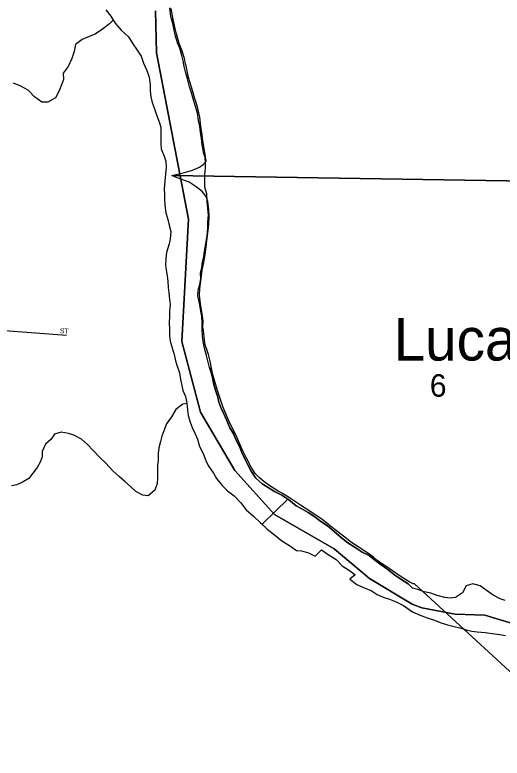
# Model space of a CAD drawing. Extents: x 1624196 to 2029251, y 146837 to 440034.
# Drawn here: x 1822196 to 1826991, y 309103 to 316418 of the extents above; entities that cross this region are included whole.
import ezdxf

# ---------------------------------------------------------------- set-up
doc = ezdxf.new("R2010")
doc.units = 0
for name, color, linetype in [('GM_X_Major_River', 7, 'Continuous'), ('GM_X_Minor_River', 7, 'Continuous'), ('GM_X_Section', 7, 'Continuous'), ('GM_X_Section_Text', 7, 'Continuous'), ('GM_X_Township', 7, 'Continuous'), ('GM_X_Township_Subdivision', 7, 'Continuous'), ('GM_X_Township_Subdivision_Text', 7, 'Continuous'), ('GM_X_Unincorporated_Text', 7, 'Continuous')]:
    doc.layers.add(name, color=color, linetype=linetype)

msp = doc.modelspace()

# ---------------------------------------------------------------- linework, layer by layer
at = {"layer": 'GM_X_Major_River'}
for p, q in [((1824628.7, 311404.7), (1824881.1, 311652.2)), ((1824881.1, 311652.2), (1824628.7, 311404.7))]:
    msp.add_line(p, q, dxfattribs=at)
for points in [[(1823091.5, 316466.6), (1823139.2, 316404.1), (1823183, 316337.6), (1823242.7, 316269), (1823314.6, 316202.4), (1823356.3, 316133.9), (1823392, 316081.5), (1823437.8, 316013), (1823461.4, 315942.6), (1823495, 315870.1), (1823516.7, 315803.8), (1823528.2, 315731.5), (1823527.8, 315669.2), (1823533.5, 315611), (1823545.2, 315556.8), (1823564.9, 315502.5), (1823590.5, 315434.1), (1823614.2, 315363.7), (1823631.9, 315311.4), (1823633.5, 315255.2), (1823633.2, 315205), (1823630.8, 315150.8), (1823636.5, 315098.6), (1823664.1, 315028.2), (1823679.9, 314978), (1823683.5, 314919.7), (1823679, 314851.5), (1823670.6, 314781.3), (1823666, 314705.1), (1823667.7, 314650.9), (1823667.4, 314600.7), (1823671, 314546.5), (1823682.6, 314470.2), (1823696.3, 314417.9), (1823713.9, 314349.6), (1823729.5, 314287.3), (1823725, 314213), (1823714.7, 314163), (1823688, 314080.8), (1823681.6, 314016.6), (1823679.2, 313956.4), (1823684.9, 313904.2), (1823694.6, 313850), (1823702.2, 313793.8), (1823705.8, 313733.5), (1823709.5, 313681.3), (1823717.1, 313619.1), (1823722.8, 313568.8), (1823718.4, 313502.6), (1823718, 313450.5), (1823715.6, 313390.3), (1823717.2, 313320), (1823716.8, 313259.8), (1823724.5, 313207.6), (1823742.1, 313141.3), (1823761.7, 313074.9), (1823777.4, 313012.6), (1823793.1, 312960.3), (1823814.8, 312896), (1823824.4, 312829.7)], [(1824112.2, 312948.4), (1824098.5, 312998.6), (1824082.8, 313067), (1824063.2, 313137.3), (1824049.6, 313203.6), (1824041.9, 313255.9), (1824040.4, 313328.1), (1824038.7, 313380.3), (1824035.2, 313452.6), (1824025.5, 313502.8), (1824011.9, 313579.2), (1823996.4, 313653.5), (1824000.7, 313707.7), (1824017.2, 313765.8), (1824025.6, 313819.9), (1824023.9, 313878.1), (1824034.3, 313930.2), (1824042.7, 313988.4), (1824055.1, 314038.5), (1824063.4, 314088.6), (1824084.4, 314224.9), (1824090.7, 314275.1), (1824093.1, 314327.2), (1824095.4, 314377.4), (1824099.9, 314449.6), (1824094.3, 314513.9), (1824088.7, 314582.1), (1824083.2, 314656.4), (1824065.6, 314722.8), (1824063.9, 314775), (1824066.4, 314845.2), (1824070.8, 314909.4), (1824073.2, 314959.5), (1824067.5, 315013.8), (1824051.8, 315064), (1824038.2, 315142.4), (1824032.6, 315202.6), (1824022.9, 315258.9), (1824017.3, 315321.1), (1824003.6, 315377.4), (1823992.1, 315449.7), (1823974.4, 315516), (1823952.8, 315582.4), (1823929.2, 315660.8), (1823915.5, 315711.1), (1823893.9, 315787.5), (1823876.3, 315857.8), (1823862.6, 315910.1), (1823850.9, 315966.3), (1823839.2, 316018.6), (1823817.6, 316089), (1823795.9, 316141.3), (1823776.2, 316209.6), (1823764.6, 316265.9), (1823749, 316334.2), (1823729.3, 316402.6), (1823719.9, 316486.9)], [(1824881.1, 311652.2), (1824822.5, 311691.8), (1824750.5, 311728.4), (1824688.5, 311764.9), (1824630.5, 311801.3), (1824566.7, 311857.9), (1824521, 311928.4), (1824489.3, 311988.8), (1824463.5, 312041.2), (1824427.8, 312111.6), (1824406.1, 312170), (1824370.5, 312238.4), (1824346.7, 312294.7), (1824311, 312353.1), (1824279.4, 312431.6), (1824247.7, 312498), (1824222, 312552.4), (1824204.3, 312606.7), (1824192.6, 312656.9), (1824168.9, 312723.3), (1824155.2, 312781.6), (1824139.6, 312845.9), (1824127.9, 312898.1), (1824112.2, 312948.4)], [(1824112.2, 312948.4), (1824127.9, 312898.1), (1824139.6, 312845.9), (1824155.2, 312781.6), (1824168.9, 312723.3), (1824192.6, 312656.9), (1824204.3, 312606.7), (1824222, 312552.4), (1824247.7, 312498), (1824279.4, 312431.6), (1824311, 312353.1), (1824346.7, 312294.7), (1824370.5, 312238.4), (1824406.1, 312170), (1824427.8, 312111.6), (1824463.5, 312041.2), (1824489.3, 311988.8), (1824521, 311928.4), (1824566.7, 311857.9), (1824630.5, 311801.3), (1824688.5, 311764.9), (1824750.5, 311728.4), (1824822.5, 311691.8), (1824888.5, 311647.3), (1824964.3, 311586.6), (1825014.3, 311560.2), (1825082.3, 311521.7), (1825138.3, 311485.2), (1825208.2, 311430.6), (1825272.1, 311388.1), (1825338, 311333.5), (1825409.9, 311272.8), (1825471.8, 311222.3), (1825545.7, 311175.7), (1825613.7, 311131.1), (1825681.7, 311098.6), (1825733.6, 311056.2), (1825799.5, 311005.6), (1825865.5, 310961), (1825935.3, 310902.4), (1825995.3, 310863.9), (1826065.1, 310819.7), (1826108.9, 310776.2)], [(1823824.4, 312829.7), (1823838, 312771.4), (1823847.8, 312721.2), (1823873.5, 312660.8), (1823887.1, 312596.5), (1823894.7, 312528.2), (1823902.3, 312474), (1823920, 312409.7), (1823939.7, 312357.4), (1823971.4, 312295), (1823993.1, 312240.7), (1824012.7, 312170.3), (1824048.4, 312099.8), (1824076.1, 312033.5), (1824097.8, 311983.1), (1824149.5, 311908.6), (1824179.3, 311854.2), (1824237.1, 311787.6), (1824286.9, 311735.2), (1824352.8, 311684.6), (1824420.6, 311614), (1824472.3, 311545.4), (1824544.2, 311484.8), (1824612, 311420.1), (1824628.7, 311404.7)], [(1823824.4, 312829.7), (1823838, 312771.4), (1823847.8, 312721.2), (1823873.5, 312660.8), (1823887.1, 312596.5), (1823894.7, 312528.2), (1823902.3, 312474), (1823920, 312409.7), (1823939.7, 312357.4), (1823971.4, 312295), (1823993.1, 312240.7), (1824012.7, 312170.3), (1824048.4, 312099.8), (1824076.1, 312033.5), (1824097.8, 311983.1), (1824149.5, 311908.6), (1824179.3, 311854.2), (1824237.1, 311787.6), (1824286.9, 311735.2), (1824352.8, 311684.6), (1824420.6, 311614), (1824472.3, 311545.4), (1824544.2, 311484.8), (1824612, 311420.1), (1824679.8, 311357.5), (1824749.7, 311300.9), (1824823.6, 311240.3), (1824899.6, 311195.6), (1824967.5, 311145.1), (1825017.6, 311142.8), (1825085.7, 311122.3), (1825151.8, 311091.8), (1825214.4, 311153.6), (1825280.3, 311107.1), (1825356.3, 311058.4), (1825416.1, 310995.9), (1825488.1, 310951.3), (1825544, 310906.8), (1825493.5, 310862.9), (1825561.4, 310810.4), (1825633.5, 310777.8), (1825701.5, 310753.3), (1825759.5, 310712.8), (1825821.6, 310688.4), (1825883.6, 310667.9), (1825947.7, 310641.5), (1826021.6, 310604.3), (1826107.6, 310541.8)], [(1826108.9, 310776.2), (1826065.1, 310819.7), (1825995.3, 310863.9), (1825935.3, 310902.4), (1825865.5, 310961), (1825799.5, 311005.6), (1825733.6, 311056.2), (1825681.7, 311098.6), (1825613.7, 311131.1), (1825545.7, 311175.7), (1825471.8, 311222.3), (1825409.9, 311272.8), (1825338, 311333.5), (1825272.1, 311388.1), (1825208.2, 311430.6), (1825138.3, 311485.2), (1825082.3, 311521.7), (1825014.3, 311560.2), (1824964.3, 311586.6), (1824888.5, 311647.3), (1824881.1, 311652.2)], [(1824628.7, 311404.7), (1824679.8, 311357.5), (1824749.7, 311300.9), (1824823.6, 311240.3), (1824899.6, 311195.6), (1824967.5, 311145.1), (1825017.6, 311142.8), (1825085.7, 311122.3), (1825151.8, 311091.8), (1825214.4, 311153.6), (1825280.3, 311107.1), (1825356.3, 311058.4), (1825416.1, 310995.9), (1825488.1, 310951.3), (1825544, 310906.8), (1825493.5, 310862.9), (1825561.4, 310810.4), (1825633.5, 310777.8), (1825701.5, 310753.3), (1825759.5, 310712.8), (1825821.6, 310688.4), (1825883.6, 310667.9), (1825947.7, 310641.5), (1826021.6, 310604.3), (1826107.6, 310541.8)], [(1827021.9, 310656), (1826971.9, 310669.9), (1826903.8, 310705.8), (1826833.7, 310757.7), (1826773.7, 310797.6), (1826703.7, 310817.5), (1826635.7, 310799.3), (1826599.9, 310729.1), (1826532, 310684.9), (1826478.1, 310678.8), (1826426.1, 310682.6), (1826350.1, 310702.5), (1826290.1, 310726.4), (1826222.1, 310740.3), (1826162, 310762.1), (1826108.9, 310776.2)], [(1826107.6, 310541.8), (1826184.6, 310509.8), (1826254.6, 310483.9), (1826324.6, 310462.1), (1826380.7, 310438.2), (1826452.7, 310416.3), (1826518.7, 310398.4), (1826574.7, 310384.5), (1826636.7, 310364.6), (1826692.7, 310352.8), (1826744.7, 310346.9), (1826822.7, 310341), (1826892.7, 310331.2), (1826968.7, 310321.3), (1827022.7, 310309.5)]]:
    msp.add_lwpolyline(points, dxfattribs=at)
at = {"layer": 'GM_X_Minor_River'}
for points in [[(1823163.4, 316367.4), (1823126.7, 316329.9), (1823058.1, 316278.2), (1822985.5, 316228.4), (1822925.2, 316206.7), (1822856.7, 316177), (1822792.2, 316125.2), (1822777.7, 316057.1), (1822757.2, 315987), (1822720.5, 315910.9), (1822671.9, 315845), (1822675.5, 315780.7), (1822653.1, 315728.7), (1822632.6, 315670.6), (1822596.1, 315600.6), (1822521.5, 315558.9), (1822461.3, 315557.2), (1822389.4, 315611.9), (1822327.6, 315676.5), (1822253.6, 315715), (1822183.5, 315745.6)], [(1823887.5, 312592.8), (1823848.9, 312586.7), (1823778.3, 312535), (1823737.7, 312461), (1823687, 312393), (1823662.5, 312322.9), (1823642.1, 312272.9), (1823627.7, 312218.8), (1823611.2, 312156.7), (1823606.9, 312102.5), (1823606.4, 312034.3), (1823600.1, 311984.1), (1823599.2, 311857.7), (1823594.9, 311805.5), (1823574.4, 311741.5), (1823507.8, 311685.7), (1823455.6, 311692), (1823387.6, 311726.5), (1823333.8, 311777), (1823277.9, 311825.5), (1823224, 311872), (1823158.1, 311930.6), (1823090.4, 312007.3), (1823032.5, 312061.8), (1822964.7, 312130.5), (1822910.9, 312189), (1822851.1, 312243.5), (1822777.1, 312282.1), (1822725, 312296.5), (1822650.8, 312311), (1822586.4, 312291.3), (1822548, 312239.3), (1822495.5, 312193.5), (1822462.9, 312119.4), (1822464.5, 312067.2), (1822444.1, 312017.2), (1822415.7, 311963.2), (1822371.2, 311907.2), (1822332.7, 311855.3), (1822276.3, 311821.5), (1822213.9, 311793.8), (1822163.6, 311782)]]:
    msp.add_lwpolyline(points, dxfattribs=at)
at = {"layer": 'GM_X_Section'}
for points in [[(1828477, 314760.9), (1823739.3, 314837.9), (1823865.4, 314865.1), (1823943.6, 314888.7), (1824013.8, 314918.2), (1824047.9, 314944), (1824078.2, 314979.8), (1824064.7, 315063.9), (1824041.5, 315200.1), (1824037.7, 315238.1), (1824026.2, 315320.2), (1824016.8, 315412.2), (1823997.3, 315496.4), (1823977.8, 315566.5), (1823967.9, 315592.5), (1823942.4, 315672.7), (1823905.2, 315800.9), (1823899.4, 315839), (1823887.7, 315881), (1823883.8, 315903.1), (1823874, 315937.1), (1823864.3, 315987.2), (1823840.8, 316059.3), (1823813.3, 316135.5), (1823787.9, 316231.6), (1823774.2, 316283.8), (1823752.7, 316371.9), (1823735.4, 316482)], [(1827995.9, 309103), (1826130.1, 310819.1), (1826116.6, 310819.2), (1826076.7, 310837.4), (1825989, 310894), (1825913.4, 310946.4), (1825847.6, 310992.8), (1825813.8, 311013.1), (1825758, 311051.4), (1825726.2, 311079.6), (1825640.5, 311140.1), (1825509, 311224.9), (1825431.4, 311287.4), (1825347.8, 311349.9), (1825282.2, 311402.3), (1825220.4, 311450.7), (1825116.9, 311521.4), (1825005.3, 311592.1), (1824887.8, 311670.8), (1824830, 311709.1), (1824788.1, 311731.4), (1824696.5, 311790), (1824644.7, 311824.3), (1824602.9, 311860.5), (1824577.8, 311887.2), (1824561.2, 311904.8), (1824519.6, 311967.1), (1824480.1, 312047.3), (1824432.1, 312141.8), (1824369.6, 312284), (1824312.3, 312398.3), (1824245.2, 312554.7), (1824186.3, 312731.1), (1824141.3, 312889.4), (1824116, 313009.5), (1824100.4, 313075.7), (1824090.6, 313103.7), (1824069, 313169.9), (1824063.3, 313215.9), (1824051.9, 313316), (1824046.1, 313346), (1824048.4, 313402), (1824042.7, 313454), (1824023.5, 313574.2), (1824012, 313658.2), (1824016.4, 313724.2), (1824024.9, 313798.2), (1824033.2, 313850.1), (1824037.5, 313904.1), (1824054, 313982), (1824068.5, 314059.9), (1824079, 314135.8), (1824083.1, 314165.8), (1824093.8, 314269.7), (1824104.3, 314357.7), (1824106.8, 314433.6), (1824105.2, 314499.7), (1824095.7, 314579.7), (1824078, 314629.8), (1824038.3, 314678.1), (1823980.6, 314726.4), (1823910.9, 314770.9), (1823793.1, 314815.6), (1823739.3, 314837.9), (1828477, 314760.9)]]:
    msp.add_lwpolyline(points, dxfattribs=at)
at = {"layer": 'GM_X_Township'}
for points in [[(1823578.9, 316457.5), (1823590, 316045.7), (1823905, 314407.4), (1823839.4, 313203.2), (1824024.1, 312508.7), (1824360.2, 311934.5), (1824750.8, 311500.4), (1825337.2, 311164.3), (1825684.5, 310871.6), (1826104.4, 310617.4), (1826199.9, 310581.9), (1826528.9, 310519.1), (1826820.7, 310509), (1827135.3, 310414.5)], [(1827135.3, 310414.5), (1826820.7, 310509), (1826528.9, 310519.1), (1826199.9, 310581.9), (1826104.4, 310617.4), (1825684.5, 310871.6), (1825337.2, 311164.3), (1824750.8, 311500.4), (1824360.2, 311934.5), (1824024.1, 312508.7), (1823839.4, 313203.2), (1823905, 314407.4), (1823590, 316045.7), (1823578.9, 316457.5)]]:
    msp.add_lwpolyline(points, dxfattribs=at)
at = {"layer": 'GM_X_Township_Subdivision'}
msp.add_lwpolyline([(1821818.3, 313313.2), (1822048.7, 313313.6), (1822704.3, 313265.4)], dxfattribs=at)

# ---------------------------------------------------------------- texts
at = {"layer": 'GM_X_Section_Text'}
msp.add_text('6', height=221, rotation=0.00001, dxfattribs=at).set_placement((1826279.3, 312660.2))
at = {"layer": 'GM_X_Township_Subdivision_Text'}
msp.add_text('ST', height=50, rotation=356.42622, dxfattribs=at).set_placement((1822636.6, 313285.3))
at = {"layer": 'GM_X_Unincorporated_Text'}
msp.add_text('Lucasville', height=417, rotation=0.00001, dxfattribs=at).set_placement((1825922.8, 313016.1))

doc.saveas('drawing.dxf')
